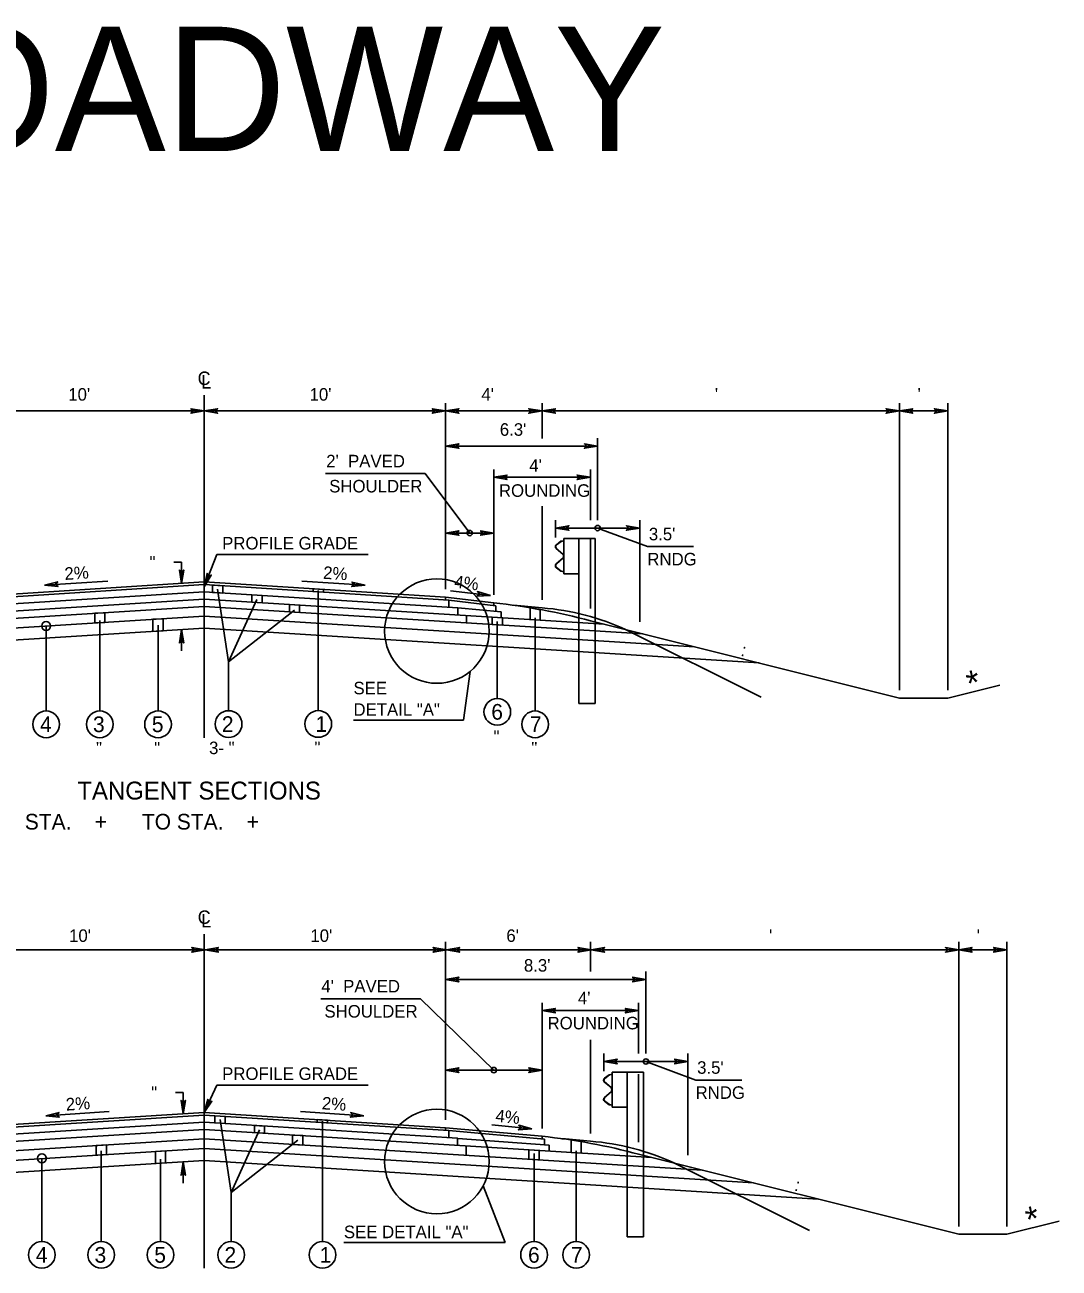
# Model space of a CAD drawing. Extents: x -592 to 1199, y -590 to 416.
# Drawn here: x -350.2 to -234.8, y -203.9 to -65 of the extents above; entities that cross this region are included whole.
import ezdxf

# ---------------------------------------------------------------- set-up
doc = ezdxf.new("R2010")
doc.units = 0
doc.layers.add('1', color=7, linetype='Continuous')
doc.layers.add('Des_ Drain_ Ftrs', color=7, linetype='Continuous')

msp = doc.modelspace()

# ---------------------------------------------------------------- linework, layer by layer
at = {"layer": '1'}
for p, q in [((-330.22, -144.63), (-330.22, -106.38)), ((-330.22, -108.14), (-357.16, -108.14)), ((-330.22, -108.14), (-303.27, -108.14)), ((-303.27, -128.06), (-303.27, -107.26)), ((-303.27, -108.14), (-292.5, -108.14)), ((-292.5, -111.21), (-292.5, -107.26)), ((-292.5, -108.14), (-252.6, -108.14)), ((-252.6, -139.33), (-252.6, -107.26)), ((-252.6, -108.14), (-247.21, -108.14)), ((-247.21, -139.33), (-247.21, -107.26)), ((-303.27, -112.06), (-286.3, -112.06)), ((-286.3, -120.34), (-286.3, -111.18)), ((-305.54, -115.14), (-316.68, -115.14)), ((-300.58, -121.78), (-305.54, -115.14)), ((-297.89, -128.69), (-297.89, -114.67)), ((-287.11, -120.34), (-287.11, -114.67)), ((-297.89, -115.55), (-287.11, -115.55)), ((-292.5, -129.25), (-292.5, -118.77)), ((-290.99, -122.29), (-290.99, -120.34)), ((-281.6, -131.7), (-281.6, -120.34)), ((-303.27, -121.78), (-297.89, -121.78)), ((-290.99, -121.22), (-281.6, -121.22)), ((-286.3, -121.22), (-280.74, -123.29)), ((-290.92, -123.51), (-290.19, -124.14)), ((-290.39, -122.69), (-290.91, -123.08)), ((-290.9, -123.49), (-290.17, -124.12)), ((-290.38, -122.72), (-290.89, -123.1)), ((-290.08, -122.63), (-290.39, -122.69)), ((-290.08, -122.66), (-290.38, -122.72)), ((-290.08, -122.4), (-290.08, -126.34)), ((-290.08, -122.4), (-288.39, -122.4)), ((-288.39, -122.4), (-288.39, -140.8)), ((-286.57, -122.4), (-288.39, -122.4)), ((-287.11, -130.22), (-287.11, -122.32)), ((-286.57, -122.4), (-286.57, -140.8)), ((-280.74, -123.29), (-275.58, -123.29)), ((-330.21, -127.77), (-328.83, -124.19)), ((-311.91, -124.19), (-328.83, -124.19)), ((-290.19, -124.6), (-290.92, -125.23)), ((-290.17, -124.62), (-290.9, -125.25)), ((-290.11, -124.33), (-290.11, -124.41)), ((-290.08, -124.33), (-290.08, -124.41)), ((-332.75, -125.04), (-333.63, -125.04)), ((-332.75, -125.04), (-332.75, -127.4)), ((-290.91, -125.66), (-290.39, -126.05)), ((-290.89, -125.64), (-290.38, -126.02)), ((-290.39, -126.05), (-290.08, -126.11)), ((-290.38, -126.02), (-290.08, -126.08)), ((-290.08, -126.34), (-288.39, -126.34)), ((-357.52, -129.26), (-330.22, -127.54)), ((-357.16, -128.94), (-330.22, -127.24)), ((-340.97, -127.14), (-348.04, -127.58)), ((-303.27, -128.94), (-330.22, -127.24)), ((-302.91, -129.26), (-330.22, -127.54)), ((-319.34, -127.16), (-312.26, -127.59)), ((-358.51, -130.13), (-330.22, -128.35)), ((-301.92, -130.13), (-330.22, -128.35)), ((-328.73, -128.06), (-327.5, -136.16)), ((-317.49, -128.19), (-317.49, -141.62)), ((-303.27, -129.24), (-303.27, -128.94)), ((-297.89, -129.57), (-303.27, -128.94)), ((-298.27, -128.74), (-302.74, -128.22)), ((-379.2, -133.05), (-330.22, -129.97)), ((-374.88, -131.97), (-330.22, -129.16)), ((-285.57, -131.97), (-330.22, -129.16)), ((-281.25, -133.05), (-330.22, -129.97)), ((-324.33, -129.18), (-327.5, -136.16)), ((-320.14, -130.4), (-327.5, -136.16)), ((-302.91, -129.26), (-302.91, -130.07)), ((-297.65, -129.9), (-302.91, -129.26)), ((-301.92, -130.13), (-301.92, -130.94)), ((-297.06, -130.56), (-301.92, -130.13)), ((-297.89, -129.87), (-297.89, -129.57)), ((-297.65, -129.9), (-297.65, -130.51)), ((-290.99, -130.35), (-290.99, -130.35)), ((-384.97, -134.49), (-330.22, -131.05)), ((-341.88, -131.54), (-341.88, -141.65)), ((-275.48, -134.49), (-330.22, -131.05)), ((-300.93, -131), (-300.93, -131.81)), ((-297.5, -131.67), (-297.5, -140.26)), ((-297.06, -130.56), (-297.06, -131.24)), ((-293.28, -131.26), (-293.28, -141.65)), ((-287.11, -131.58), (-252.6, -140.21)), ((-392.17, -136.29), (-330.22, -132.4)), ((-347.87, -132.16), (-347.87, -141.65)), ((-335.38, -132.05), (-335.38, -141.65)), ((-332.75, -132.56), (-332.75, -134.92)), ((-268.28, -136.29), (-330.22, -132.4)), ((-283.1, -132.58), (-268.05, -140.11)), ((-327.5, -136.16), (-327.5, -141.63)), ((-300.54, -137.24), (-301.26, -142.69)), ((-241.39, -138.75), (-247.21, -140.21)), ((-252.6, -140.21), (-247.21, -140.21)), ((-286.57, -140.8), (-288.39, -140.8)), ((-313.57, -142.69), (-301.26, -142.69)), ((-330.21, -203.88), (-330.21, -166.56)), ((-303.27, -187.31), (-303.27, -167.44)), ((-287.11, -170.76), (-287.11, -167.44)), ((-245.99, -199.21), (-245.99, -167.44)), ((-240.6, -199.21), (-240.6, -167.44)), ((-330.12, -168.32), (-357.07, -168.32)), ((-330.12, -168.32), (-303.18, -168.32)), ((-303.18, -168.32), (-287.02, -168.32)), ((-287.02, -168.32), (-245.99, -168.32)), ((-245.99, -168.32), (-240.6, -168.32)), ((-280.91, -179.92), (-280.91, -170.76)), ((-303.27, -171.64), (-280.91, -171.64)), ((-306.07, -173.79), (-317.21, -173.79)), ((-297.89, -181.76), (-306.07, -173.79)), ((-292.5, -188.27), (-292.5, -174.23)), ((-281.72, -179.92), (-281.72, -174.23)), ((-292.5, -175.11), (-281.72, -175.11)), ((-287.11, -188.83), (-287.11, -178.38)), ((-285.6, -181.87), (-285.6, -179.92)), ((-276.22, -191.26), (-276.22, -179.92)), ((-303.27, -181.76), (-292.5, -181.76)), ((-285.6, -180.8), (-276.22, -180.8)), ((-280.91, -180.8), (-275.35, -182.87)), ((-285.53, -183.09), (-284.8, -183.72)), ((-285, -182.27), (-285.52, -182.66)), ((-285.52, -183.07), (-284.78, -183.7)), ((-284.99, -182.29), (-285.5, -182.68)), ((-284.69, -182.21), (-285, -182.27)), ((-284.69, -182.24), (-284.99, -182.29)), ((-284.69, -181.98), (-284.69, -185.91)), ((-284.69, -181.98), (-283, -181.98)), ((-283, -181.98), (-283, -200.38)), ((-281.18, -181.98), (-283, -181.98)), ((-281.72, -189.8), (-281.72, -182.23)), ((-281.18, -181.98), (-281.18, -200.38)), ((-275.35, -182.87), (-270.2, -182.87)), ((-332.56, -184.27), (-333.44, -184.27)), ((-332.56, -184.27), (-332.56, -186.64)), ((-330.21, -186.49), (-328.83, -183.45)), ((-311.91, -183.45), (-328.83, -183.45)), ((-284.8, -184.17), (-285.53, -184.81)), ((-284.78, -184.2), (-285.52, -184.83)), ((-284.72, -183.91), (-284.72, -183.99)), ((-284.69, -183.91), (-284.69, -183.99)), ((-285.52, -185.24), (-285, -185.63)), ((-285.5, -185.22), (-284.99, -185.6)), ((-285, -185.63), (-284.69, -185.69)), ((-284.99, -185.6), (-284.69, -185.66)), ((-284.69, -185.91), (-283, -185.91)), ((-357.52, -188.51), (-330.21, -186.79)), ((-357.16, -188.18), (-330.21, -186.49)), ((-340.82, -186.39), (-347.9, -186.85)), ((-303.27, -188.19), (-330.21, -186.5)), ((-302.91, -188.51), (-330.21, -186.79)), ((-328.46, -187.26), (-327.22, -195.42)), ((-319.49, -186.4), (-312.41, -186.86)), ((-380.2, -191.52), (-330.21, -188.38)), ((-358.49, -189.36), (-330.21, -187.59)), ((-301.93, -189.37), (-330.21, -187.59)), ((-280.25, -191.53), (-330.21, -188.39)), ((-324.05, -188.43), (-327.22, -195.42)), ((-317.02, -187.47), (-317.02, -200.91)), ((-303.27, -188.49), (-303.27, -188.19)), ((-292.5, -189.15), (-303.27, -188.19)), ((-302.91, -188.51), (-302.91, -189.31)), ((-292.25, -189.47), (-302.9, -188.51)), ((-293.65, -188.3), (-298.13, -187.89)), ((-385.82, -192.93), (-330.21, -189.43)), ((-274.63, -192.93), (-330.21, -189.44)), ((-319.77, -189.59), (-327.22, -195.42)), ((-301.93, -189.37), (-301.93, -190.17)), ((-291.7, -190.13), (-301.92, -189.38)), ((-300.96, -190.23), (-300.96, -191.28)), ((-292.5, -189.45), (-292.5, -189.15)), ((-292.25, -189.47), (-292.25, -190.08)), ((-291.7, -190.13), (-291.7, -190.81)), ((-285.6, -189.93), (-285.6, -189.93)), ((-391.55, -194.36), (-330.21, -190.51)), ((-348.35, -191.61), (-348.35, -200.91)), ((-341.72, -190.78), (-341.72, -200.91)), ((-268.91, -194.36), (-330.21, -190.51)), ((-293.4, -191.06), (-293.4, -200.91)), ((-288.69, -190.78), (-288.69, -200.91)), ((-281.72, -191.16), (-245.99, -200.09)), ((-398.78, -196.17), (-330.21, -191.86)), ((-335.1, -191.7), (-335.1, -200.91)), ((-332.57, -192.01), (-332.57, -194.38)), ((-261.67, -196.17), (-330.21, -191.86)), ((-277.72, -192.16), (-262.66, -199.69)), ((-327.22, -195.42), (-327.22, -200.91)), ((-299.07, -194.69), (-296.63, -201.03)), ((-234.78, -198.64), (-240.6, -200.09)), ((-314.63, -201.03), (-296.63, -201.03)), ((-281.18, -200.38), (-283, -200.38)), ((-245.99, -200.09), (-240.6, -200.09))]:
    msp.add_line(p, q, dxfattribs=at)
for points in [[(-329.31, -127.6), (-328.16, -127.67), (-328.16, -128.48), (-329.31, -128.41)], [(-324.91, -128.69), (-323.76, -128.76), (-323.76, -129.57), (-324.91, -129.49)], [(-318.07, -128.01), (-316.92, -128.08), (-316.92, -128.38), (-318.07, -128.31)], [(-320.71, -129.76), (-319.57, -129.83), (-319.57, -130.64), (-320.71, -130.57)], [(-293.85, -130.14), (-292.7, -130.34), (-292.7, -131.52), (-293.85, -131.45)], [(-342.45, -130.74), (-341.31, -130.67), (-341.31, -131.75), (-342.45, -131.82)], [(-335.95, -131.41), (-334.81, -131.34), (-334.81, -132.69), (-335.95, -132.76)], [(-298.08, -131.18), (-296.93, -131.25), (-296.93, -132.06), (-298.08, -131.99)], [(-329.04, -186.87), (-327.89, -186.94), (-327.89, -187.74), (-329.04, -187.66)], [(-317.6, -187.29), (-316.45, -187.36), (-316.45, -187.66), (-317.6, -187.59)], [(-324.62, -187.94), (-323.48, -188.01), (-323.48, -188.81), (-324.62, -188.74)], [(-342.29, -190.19), (-341.15, -190.12), (-341.15, -191.19), (-342.29, -191.26)], [(-320.35, -189.01), (-319.2, -189.08), (-319.2, -190.13), (-320.35, -190.06)], [(-289.26, -189.56), (-288.12, -189.75), (-288.12, -191.03), (-289.26, -190.96)], [(-335.68, -190.85), (-334.53, -190.78), (-334.53, -192.13), (-335.68, -192.2)], [(-293.98, -190.67), (-292.83, -190.74), (-292.83, -191.79), (-293.98, -191.72)]]:
    msp.add_lwpolyline(points, close=True, dxfattribs=at)
for centre, radius in [((-300.58, -121.78), 0.3), ((-286.3, -121.22), 0.3), ((-304.24, -132.72), 5.84), ((-347.87, -132.16), 0.5), ((-327.5, -143.11), 1.49), ((-317.49, -143.1), 1.49), ((-297.5, -141.75), 1.49), ((-347.87, -143.14), 1.49), ((-341.88, -143.14), 1.49), ((-335.38, -143.14), 1.49), ((-293.28, -143.14), 1.49), ((-280.91, -180.8), 0.3), ((-297.89, -181.76), 0.3), ((-304.24, -191.97), 5.84), ((-348.35, -191.61), 0.5), ((-348.35, -202.39), 1.49), ((-341.72, -202.39), 1.49), ((-335.1, -202.39), 1.49), ((-327.22, -202.39), 1.49), ((-317.02, -202.39), 1.49), ((-293.4, -202.39), 1.49), ((-288.69, -202.39), 1.49)]:
    msp.add_circle(centre, radius, dxfattribs=at)
for centre, radius, start, end in [((-290.74, -123.3), 0.278, 126.9799, 229.021), ((-290.74, -123.3), 0.249, 126.9799, 229.021), ((-290.35, -124.33), 0.249, 0, 49.0365), ((-290.35, -124.41), 0.249, 310.9635, 0), ((-290.35, -124.33), 0.278, 0, 49.0365), ((-290.35, -124.41), 0.278, 310.9635, 0), ((-290.74, -125.44), 0.278, 130.979, 233.0201), ((-290.74, -125.44), 0.249, 130.979, 233.0201), ((-304.77, -196.41), 67.19, 74.7593, 84.1179), ((-303.31, -230.79), 101.24, 83.8633, 85.6775), ((-294.61, -157.42), 27.37, 65.1374, 85.5513), ((-285.35, -182.88), 0.278, 126.9799, 229.021), ((-285.35, -182.88), 0.249, 126.9799, 229.021), ((-284.97, -183.91), 0.249, 0, 49.0365), ((-284.97, -183.99), 0.249, 310.9635, 0), ((-284.97, -183.91), 0.278, 0, 49.0365), ((-284.97, -183.99), 0.278, 310.9635, 0), ((-285.35, -185.02), 0.278, 130.979, 233.0201), ((-285.35, -185.02), 0.249, 130.979, 233.0201), ((-299.38, -255.99), 67.19, 74.7611, 84.1196), ((-297.92, -290.37), 101.24, 83.8633, 85.6775), ((-289.22, -216.99), 27.37, 65.1374, 85.5513)]:
    msp.add_arc(centre, radius, start, end, dxfattribs=at)
at = {"layer": 'Des_ Drain_ Ftrs'}
for points in [[(-330.22, -108.14), (-331.7, -108.39), (-331.41, -108.14), (-331.7, -107.89)], [(-330.22, -108.14), (-328.73, -108.39), (-329.02, -108.14), (-328.73, -107.89)], [(-303.27, -108.14), (-304.76, -108.39), (-304.47, -108.14), (-304.76, -107.89)], [(-303.27, -108.14), (-301.79, -108.39), (-302.08, -108.14), (-301.79, -107.89)], [(-292.5, -108.14), (-293.99, -108.39), (-293.69, -108.14), (-293.99, -107.89)], [(-292.5, -108.14), (-291.01, -108.39), (-291.3, -108.14), (-291.01, -107.89)], [(-252.6, -108.14), (-254.09, -108.39), (-253.79, -108.14), (-254.09, -107.89)], [(-252.6, -108.14), (-251.11, -108.39), (-251.41, -108.14), (-251.11, -107.89)], [(-247.21, -108.14), (-248.7, -108.39), (-248.41, -108.14), (-248.7, -107.89)], [(-303.27, -112.06), (-301.78, -112.31), (-302.08, -112.06), (-301.78, -111.82)], [(-286.3, -112.06), (-287.78, -112.31), (-287.49, -112.06), (-287.78, -111.82)], [(-297.89, -115.55), (-296.4, -115.8), (-296.69, -115.55), (-296.4, -115.3)], [(-287.11, -115.55), (-288.6, -115.8), (-288.3, -115.55), (-288.6, -115.3)], [(-303.27, -121.78), (-301.79, -122.03), (-302.08, -121.78), (-301.79, -121.53)], [(-297.89, -121.78), (-299.37, -122.03), (-299.08, -121.78), (-299.37, -121.53)], [(-290.99, -121.22), (-289.5, -121.47), (-289.8, -121.22), (-289.5, -120.97)], [(-281.6, -121.22), (-283.09, -121.47), (-282.8, -121.22), (-283.09, -120.97)], [(-332.75, -127.4), (-332.5, -125.92), (-332.75, -126.21), (-333, -125.92)], [(-330.21, -127.77), (-329.44, -126.47), (-329.78, -126.65), (-329.91, -126.29)], [(-348.04, -127.58), (-346.54, -127.73), (-346.85, -127.5), (-346.57, -127.24)], [(-312.26, -127.59), (-313.77, -127.75), (-313.46, -127.52), (-313.74, -127.25)], [(-298.27, -128.74), (-299.78, -128.82), (-299.46, -128.6), (-299.73, -128.32)], [(-332.75, -132.56), (-332.5, -134.04), (-332.75, -133.75), (-333, -134.04)], [(-330.12, -168.32), (-331.61, -168.57), (-331.32, -168.32), (-331.61, -168.07)], [(-330.12, -168.32), (-328.64, -168.57), (-328.93, -168.32), (-328.64, -168.07)], [(-303.18, -168.32), (-304.67, -168.57), (-304.38, -168.32), (-304.67, -168.07)], [(-303.18, -168.32), (-301.7, -168.57), (-301.99, -168.32), (-301.7, -168.07)], [(-287.02, -168.32), (-288.51, -168.57), (-288.21, -168.32), (-288.51, -168.07)], [(-287.02, -168.32), (-285.53, -168.57), (-285.83, -168.32), (-285.53, -168.07)], [(-245.99, -168.32), (-247.48, -168.57), (-247.19, -168.32), (-247.48, -168.07)], [(-245.99, -168.32), (-244.5, -168.57), (-244.8, -168.32), (-244.5, -168.07)], [(-240.6, -168.32), (-242.09, -168.57), (-241.8, -168.32), (-242.09, -168.07)], [(-303.27, -171.64), (-301.78, -171.89), (-302.08, -171.64), (-301.78, -171.39)], [(-280.91, -171.64), (-282.4, -171.89), (-282.1, -171.64), (-282.4, -171.39)], [(-292.5, -175.11), (-291.01, -175.36), (-291.3, -175.11), (-291.01, -174.86)], [(-281.72, -175.11), (-283.21, -175.36), (-282.91, -175.11), (-283.21, -174.86)], [(-303.27, -181.76), (-301.79, -182.01), (-302.08, -181.76), (-301.79, -181.51)], [(-292.5, -181.76), (-293.99, -182.01), (-293.69, -181.76), (-293.99, -181.51)], [(-285.6, -180.8), (-284.11, -181.05), (-284.41, -180.8), (-284.11, -180.55)], [(-276.22, -180.8), (-277.7, -181.05), (-277.41, -180.8), (-277.7, -180.55)], [(-332.56, -186.64), (-332.32, -185.15), (-332.56, -185.45), (-332.81, -185.15)], [(-330.21, -186.49), (-329.37, -185.24), (-329.72, -185.41), (-329.82, -185.04)], [(-347.9, -186.85), (-346.4, -187), (-346.71, -186.77), (-346.43, -186.5)], [(-312.41, -186.86), (-313.92, -187.01), (-313.6, -186.78), (-313.88, -186.51)], [(-293.65, -188.3), (-295.15, -188.42), (-294.83, -188.2), (-295.11, -187.92)], [(-332.57, -192.01), (-332.32, -193.5), (-332.57, -193.2), (-332.81, -193.5)]]:
    msp.add_lwpolyline(points, close=True, dxfattribs=at)

# ---------------------------------------------------------------- texts
at = {"layer": '1'}
for s, height, p in [("20' ROADWAY", 13.8979, (-404.17, -79.12)), ("10'", 1.4, (-345.4, -106.99)), ("10'", 1.4, (-318.46, -106.99)), ("4'", 1.4, (-299.28, -106.99)), ("  '", 1.4, (-274.25, -106.99)), (" '", 1.4, (-251.1, -106.99)), ("6.3'", 1.4, (-297.22, -110.91)), ("2'  PAVED", 1.4, (-316.6, -114.44)), ("4'", 1.4, (-293.93, -114.93)), ('SHOULDER', 1.4, (-316.27, -117.24)), ('ROUNDING', 1.4, (-297.32, -117.73)), ('PROFILE GRADE', 1.4, (-328.22, -123.61)), ("3.5'", 1.4, (-280.58, -122.59)), ('RNDG', 1.4, (-280.75, -125.39)), ('SEE', 1.4, (-313.56, -139.79)), ('DETAIL "A"', 1.4, (-313.56, -142.19)), ('6', 1.75, (-298.17, -142.62)), ('4', 1.75, (-348.55, -144.01)), ('3', 1.75, (-342.64, -144.01)), ('5', 1.75, (-336.07, -144.01)), ('2', 1.75, (-328.25, -143.99)), ('1', 1.75, (-317.8, -143.98)), ('7', 1.75, (-293.87, -144.01)), (' "', 1.4, (-298.45, -145.2)), (' "', 1.4, (-342.82, -146.5)), (' "', 1.4, (-336.32, -146.5)), ('3- "', 1.4, (-329.68, -146.47)), (' "', 1.4, (-318.44, -146.46)), (' "', 1.4, (-294.22, -146.5)), ('TANGENT SECTIONS', 2, (-344.39, -151.54)), ('STA.    +      TO STA.    +     ', 1.75, (-350.25, -154.89)), ("10'", 1.4, (-345.31, -167.44)), ("10'", 1.4, (-318.37, -167.44)), ("6'", 1.4, (-296.49, -167.44)), ("  '", 1.4, (-268.2, -167.44)), (" '", 1.4, (-244.49, -167.44)), ("8.3'", 1.4, (-294.53, -170.76)), ("4'  PAVED", 1.4, (-317.15, -173.09)), ("4'", 1.4, (-288.5, -174.41)), ('SHOULDER', 1.4, (-316.8, -175.89)), ('ROUNDING', 1.4, (-291.89, -177.21)), ('PROFILE GRADE', 1.4, (-328.22, -182.86)), ("3.5'", 1.4, (-275.19, -182.17)), ('RNDG', 1.4, (-275.36, -184.97)), ('SEE DETAIL "A"', 1.4, (-314.63, -200.53)), ('4', 1.75, (-349.02, -203.27)), ('3', 1.75, (-342.47, -203.27)), ('5', 1.75, (-335.8, -203.27)), ('2', 1.75, (-327.96, -203.27)), ('1', 1.75, (-317.33, -203.27)), ('6', 1.75, (-294.07, -203.27)), ('7', 1.75, (-289.28, -203.27))]:
    msp.add_text(s, height=height, dxfattribs=at).set_placement(p)
for s, height, rotation, p in [('  "', 1.4, 0.1438, (-337.36, -125.74)), ('2%', 1.4, 3.6289, (-345.78, -127.02)), ('2%', 1.4, 356.4063, (-316.98, -126.88)), ('4%', 1.4, 353.1274, (-302.36, -127.87)), (' : ', 1.4, 345.7718, (-270.9, -135.34)), ('*', 2.8, 12.8479, (-244.75, -140.02)), ('  "', 1.4, 0.1438, (-337.18, -184.98)), ('2%', 1.4, 3.7746, (-345.63, -186.29)), ('2%', 1.4, 356.1492, (-317.12, -186.13)), ('4%', 1.4, 354.472, (-297.75, -187.53)), (' : ', 1.4, 345.7718, (-264.91, -195.07)), ('*', 2.8, 12.8479, (-238.14, -199.9))]:
    msp.add_text(s, height=height, rotation=rotation, dxfattribs=at).set_placement(p)
at = {"layer": 'Des_ Drain_ Ftrs'}
for s, p in [('C', (-330.96, -105.24)), ('L', (-330.56, -105.64)), ('C', (-330.95, -165.43)), ('L', (-330.56, -165.82))]:
    msp.add_text(s, height=1.5, dxfattribs=at).set_placement(p)

doc.saveas('drawing.dxf')
